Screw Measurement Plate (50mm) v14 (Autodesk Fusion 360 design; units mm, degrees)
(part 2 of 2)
sketch "Labels, Lines (50mm)" plane through (0, 0, 10) normal (0, 0, 1) x axis (1, 0, 0)
  line L1 (-22.7442, -10.4354) -> (-22.7442, -8.6639)
  line L2 (-23.544, -10.4354) -> (-22.7442, -10.4354)
  line L3 (-25.6497, -8.6639) -> (-23.544, -10.4354)
  line L4 (-25.6497, -7.8164) -> (-25.6497, -8.6639)
  line L5 (-23.4986, -7.8164) -> (-25.6497, -7.8164)
  line L6 (-23.4986, -7.3771) -> (-23.4986, -7.8164)
  line L7 (-22.7442, -7.3771) -> (-23.4986, -7.3771)
  line L8 (-22.7442, -7.8164) -> (-22.7442, -7.3771)
  line L9 (-22.09, -7.8164) -> (-22.7442, -7.8164)
  line L10 (-22.09, -8.6639) -> (-22.09, -7.8164)
  line L11 (-22.7442, -8.6639) -> (-22.09, -8.6639)
  line L12 (-24.6001, -8.6639) -> (-23.4986, -8.6639)
  line L13 (-23.4986, -9.6) -> (-24.6001, -8.6639)
  line L14 (-23.4986, -8.6639) -> (-23.4986, -9.6)
  curve K1 (-20.2435, -9.9866) -> (-19.9713, -9.6523)
  curve K2 (-20.7162, -10.1298) -> (-20.2435, -9.9866)
  curve K3 (-21.4348, -9.7168) -> (-20.7162, -10.1298)
  curve K4 (-21.6497, -8.8645) -> (-21.4348, -9.7168)
  curve K5 (-21.3823, -7.8271) -> (-21.6497, -8.8645)
  curve K6 (-20.709, -7.4917) -> (-21.3823, -7.8271)
  curve K7 (-20.2674, -7.6254) -> (-20.709, -7.4917)
  curve K8 (-19.9713, -7.9405) -> (-20.2674, -7.6254)
  curve K9 (-19.6108, -7.5168) -> (-19.9713, -7.9405)
  curve K10 (-19.1142, -7.3771) -> (-19.6108, -7.5168)
  curve K11 (-18.6236, -7.4977) -> (-19.1142, -7.3771)
  curve K12 (-18.2714, -7.7937) -> (-18.6236, -7.4977)
  curve K13 (-18.0888, -8.2306) -> (-18.2714, -7.7937)
  curve K14 (-18.0303, -8.7881) -> (-18.0888, -8.2306)
  curve K15 (-18.1616, -9.638) -> (-18.0303, -8.7881)
  curve K16 (-18.5484, -10.0845) -> (-18.1616, -9.638)
  curve K17 (-19.119, -10.2373) -> (-18.5484, -10.0845)
  curve K18 (-19.6406, -10.094) -> (-19.119, -10.2373)
  curve K19 (-19.9713, -9.6523) -> (-19.6406, -10.094)
  curve K20 (-20.3664, -9.102) -> (-20.6589, -9.2154)
  curve K21 (-20.2554, -8.8) -> (-20.3664, -9.102)
  curve K22 (-20.3652, -8.5255) -> (-20.2554, -8.8)
  curve K23 (-20.6493, -8.418) -> (-20.3652, -8.5255)
  curve K24 (-20.9442, -8.5302) -> (-20.6493, -8.418)
  curve K25 (-21.0576, -8.8167) -> (-20.9442, -8.5302)
  curve K26 (-20.9466, -9.1044) -> (-21.0576, -8.8167)
  curve K27 (-20.6589, -9.2154) -> (-20.9466, -9.1044)
  curve K28 (-18.774, -9.1271) -> (-19.1524, -9.268)
  curve K29 (-18.6272, -8.8048) -> (-18.774, -9.1271)
  curve K30 (-18.7764, -8.492) -> (-18.6272, -8.8048)
  curve K31 (-19.1548, -8.3536) -> (-18.7764, -8.492)
  curve K32 (-19.5344, -8.4932) -> (-19.1548, -8.3536)
  curve K33 (-19.6824, -8.8167) -> (-19.5344, -8.4932)
  curve K34 (-19.5392, -9.1331) -> (-19.6824, -8.8167)
  curve K35 (-19.1524, -9.268) -> (-19.5392, -9.1331)
  line L15 (-14.09, -11.2806) -> (-17.6497, -11.2806)
  line L16 (-14.09, -12.2642) -> (-14.09, -11.2806)
  line L17 (-16.4225, -12.2642) -> (-14.09, -12.2642)
  curve K36 (-16.1289, -12.7262) -> (-16.4225, -12.2642)
  curve K37 (-15.914, -13.286) -> (-16.1289, -12.7262)
  line L18 (-16.7114, -13.286) -> (-15.914, -13.286)
  curve K38 (-17.0958, -12.5149) -> (-16.7114, -13.286)
  curve K39 (-17.6497, -12.0852) -> (-17.0958, -12.5149)
  line L19 (-17.6497, -11.2806) -> (-17.6497, -12.0852)
  line L20 (-14.09, -10.2946) -> (-14.09, -7.3771)
  curve K40 (-14.9029, -9.9902) -> (-14.09, -10.2946)
  curve K41 (-15.8018, -9.0364) -> (-14.9029, -9.9902)
  curve K42 (-16.2841, -8.4897) -> (-15.8018, -9.0364)
  curve K43 (-16.5968, -8.3703) -> (-16.2841, -8.4897)
  curve K44 (-16.8702, -8.4885) -> (-16.5968, -8.3703)
  curve K45 (-16.9836, -8.7857) -> (-16.8702, -8.4885)
  curve K46 (-16.8666, -9.0901) -> (-16.9836, -8.7857)
  curve K47 (-16.4536, -9.2489) -> (-16.8666, -9.0901)
  line L21 (-16.5324, -10.2229) -> (-16.4536, -9.2489)
  curve K48 (-17.1734, -10.0129) -> (-16.5324, -10.2229)
  curve K49 (-17.5267, -9.5819) -> (-17.1734, -10.0129)
  curve K50 (-17.6497, -8.812) -> (-17.5267, -9.5819)
  curve K51 (-17.5327, -8.0134) -> (-17.6497, -8.812)
  curve K52 (-17.1734, -7.5645) -> (-17.5327, -8.0134)
  curve K53 (-16.6302, -7.401) -> (-17.1734, -7.5645)
  curve K54 (-16.0191, -7.5884) -> (-16.6302, -7.401)
  curve K55 (-15.3792, -8.27) -> (-16.0191, -7.5884)
  curve K56 (-15.0951, -8.6627) -> (-15.3792, -8.27)
  curve K57 (-14.8826, -8.8955) -> (-15.0951, -8.6627)
  line L22 (-14.8826, -7.3771) -> (-14.8826, -8.8955)
  line L23 (-14.09, -7.3771) -> (-14.8826, -7.3771)
  line L24 (-10.09, -11.3236) -> (-13.6497, -11.3236)
  line L25 (-10.09, -12.3072) -> (-10.09, -11.3236)
  line L26 (-12.4225, -12.3072) -> (-10.09, -12.3072)
  curve K58 (-12.1289, -12.7692) -> (-12.4225, -12.3072)
  curve K59 (-11.914, -13.329) -> (-12.1289, -12.7692)
  line L27 (-12.7114, -13.329) -> (-11.914, -13.329)
  curve K60 (-13.0958, -12.5579) -> (-12.7114, -13.329)
  curve K61 (-13.6497, -12.1281) -> (-13.0958, -12.5579)
  line L28 (-13.6497, -11.3236) -> (-13.6497, -12.1281)
  line L29 (-12.6828, -8.418) -> (-12.8021, -7.4511)
  curve K62 (-12.9693, -8.5458) -> (-12.6828, -8.418)
  curve K63 (-13.0528, -8.7666) -> (-12.9693, -8.5458)
  curve K64 (-12.8141, -9.1343) -> (-13.0528, -8.7666)
  curve K65 (-12.0787, -9.2751) -> (-12.8141, -9.1343)
  curve K66 (-12.3402, -8.917) -> (-12.0787, -9.2751)
  curve K67 (-12.4249, -8.492) -> (-12.3402, -8.917)
  curve K68 (-12.0907, -7.7006) -> (-12.4249, -8.492)
  curve K69 (-11.2431, -7.3771) -> (-12.0907, -7.7006)
  curve K70 (-10.6105, -7.5406) -> (-11.2431, -7.3771)
  curve K71 (-10.1771, -7.9943) -> (-10.6105, -7.5406)
  curve K72 (-10.0303, -8.7212) -> (-10.1771, -7.9943)
  curve K73 (-10.2094, -9.564) -> (-10.0303, -8.7212)
  curve K74 (-10.7812, -10.0713) -> (-10.2094, -9.564)
  curve K75 (-11.8209, -10.2611) -> (-10.7812, -10.0713)
  curve K76 (-13.2092, -9.8624) -> (-11.8209, -10.2611)
  curve K77 (-13.6497, -8.7571) -> (-13.2092, -9.8624)
  curve K78 (-13.553, -8.0969) -> (-13.6497, -8.7571)
  curve K79 (-13.2701, -7.6946) -> (-13.553, -8.0969)
  curve K80 (-12.8021, -7.4511) -> (-13.2701, -7.6946)
  curve K81 (-10.7979, -9.0985) -> (-11.2431, -9.2417)
  curve K82 (-10.6367, -8.7475) -> (-10.7979, -9.0985)
  curve K83 (-10.7824, -8.4276) -> (-10.6367, -8.7475)
  curve K84 (-11.2169, -8.2987) -> (-10.7824, -8.4276)
  curve K85 (-11.6681, -8.4324) -> (-11.2169, -8.2987)
  curve K86 (-11.8233, -8.7642) -> (-11.6681, -8.4324)
  curve K87 (-11.6729, -9.1044) -> (-11.8233, -8.7642)
  curve K88 (-11.2431, -9.2417) -> (-11.6729, -9.1044)
  line L30 (-6.09, -13.5701) -> (-6.09, -10.6527)
  curve K89 (-6.9029, -13.2657) -> (-6.09, -13.5701)
  curve K90 (-7.8018, -12.312) -> (-6.9029, -13.2657)
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extrude "Extrude6" add sketch "Labels, Lines (50mm)" + "Labels, Pockets (M5, 4mm)" blind 0.4
place_component sketch "Labels, Lines (50mm)" + "Labels, Pockets (M5, 4mm)"
extrude "Extrude1" new body sketch "Labels, Lines (50mm)" + "Labels, Pockets (M5, 4mm)" blind 0.4
position "Position2"
copy_paste_bodies "CopyPasteBodies5"
move "Move3"
sketch "Mount Holes (Hex)" plane through (0, 0, 0) normal (0, 0, 1) x axis (1, 0, 0)
  line L1 (-27, 18) -> (-27, 10)
  line L2 (-27, 0) -> (-27, -8)
  line L3 (27, 26) -> (-31, 26)
  line L4 (-31, 26) -> (-31, 18)
  line L5 (-31, -26) -> (-31, -8)
  line L6 (27, -26) -> (-31, -26)
  line L7 (-27, 25.25) -> (-27, 18.3107)
  line L8 (-27, 25.1578) -> (-24.075, 23.4691)
  line L9 (-29.925, 23.4691) -> (-27, 25.1578)
  line L10 (-29.925, 20.0916) -> (-29.925, 23.4691)
  line L11 (-27, 18.4028) -> (-29.925, 20.0916)
  line L12 (-24.075, 20.0916) -> (-27, 18.4028)
  line L13 (-24.075, 23.4691) -> (-24.075, 20.0916)
  line L14 (-27, -15.9078) -> (-29.925, -14.2191)
  line L15 (-24.075, -14.2191) -> (-27, -15.9078)
  line L16 (-24.075, -10.8416) -> (-24.075, -14.2191)
  line L17 (-27, -9.1528) -> (-24.075, -10.8416)
  line L18 (-29.925, -10.8416) -> (-27, -9.1528)
  line L19 (-29.925, -14.2191) -> (-29.925, -10.8416)
  line L20 (24, 25.25) -> (-28, 25.25)
  line L21 (-30.25, 18.3107) -> (-27, 18.3107)
  line L22 (-27, -8.3107) -> (-30.25, -8.3107)
  line L23 (-25.3, -16.75) -> (-27, -16.75)
  line L24 (-27, -16.75) -> (-27, -8.3107)
  circle C1 centre (-27, 21.7803) radius 1.625
  circle C2 centre (-27, -12.5303) radius 1.625
  circle C3 centre (-27, 21.7803) radius 2.57
  circle C4 centre (-27, -12.5303) radius 2.57
  arc A1 centre (-25.3, -20) radius 3.25 clockwise from (-28.55, -20) to (-22.05, -20)
  point P16 (-27, 21.7803)
  point P24 (-27, 21.7803)
  point P26 (-27, -12.5303)
  point P33 (-27, -12.5303)
  point P15 (-27, 25.25)
  point P14 (-27, 18.3107)
  point P36 (-27, 18.3107)
  point P44 (-25.3, -16.75)
  point P43 (-27, -16.75)
  point P46 (-27, -16.75)
  point P39 (-27, -8.3107)
  point P45 (-27, -8.3107)
  perpendicular L3 L7
  midpoint L7 P16
  coincident P16 P24
  concentric C1 C3
  concentric C2 C4
  coincident P26 P33
  vertical L10
  vertical L19
  coincident P15 L20
  coincident P14 L21
  coincident P14 P36
  horizontal L23
  tangent A1 L23
  coincident A1 P44
  vertical L24
  coincident P43 P46
  coincident P39 P45
  midpoint P26 L24
  dimension "diaMountHole" diameter C2 = 3.25
  dimension "diaMountHole2" diameter C1 = 3.25 (= "diaMountHole")
  dimension "diaMountHex" distance L10 L13 = 5.85
  dimension "diaMagPost" diameter C3 = 5.14
  dimension "diaMagPost2" diameter C4 = 5.14 (= "diaMagPost")
  dimension "diaMountHex2" distance L15 L18 = 5.85 (= "diaMountHex")
extrude "Extrude7" cut sketch "Mount Holes (Hex)" profile of C1 C2 to an object
extrude "Extrude8" sketch "Mount Holes (Hex)" profile of C1 C2 L8 L9 L10 L11 L12 L13 C3 C4 L14 L15 L16 L17 L18 L19 blind -2.65
extrude "Extrude9" cut sketch "Mount Holes (Hex)" profile of C1 C2 C3 C4 along normal blind 5
move "Move4"
copy_paste_bodies "CopyPasteBodies11"
move "Move12"
base_feature "Base Feature1"
base_feature "Base Feature1"
rectangular_pattern "舁}" uSpaceDistance 20 vSpaceDistance 0
joint "Assemble1" alignAngle 0 alignOffsetX 0 alignOffsetY 0 alignOffsetZ 0
joint "Assemble2" alignAngle 0 alignOffsetX 0 alignOffsetY 0 alignOffsetZ 0
joint "Assemble3" alignAngle 0 alignOffsetX 0 alignOffsetY 0 alignOffsetZ 0
joint "Assemble4" alignAngle 0 alignOffsetX 0 alignOffsetY 0 alignOffsetZ 0
copy_paste "CutPaste1"
copy_paste "CutPaste2"
copy_paste "CutPaste3"
copy_paste "CutPaste4"
copy_paste_bodies "CopyPasteBodies6"
move "Move5"
sketch "Hook Hanger" plane through (0, 0, 0) normal (0, 0, 1) x axis (1, 0, 0)
  line L1 (-28, 26) -> (24, 26)
  line L2 (-31, -8.3107) -> (-31, -0.75)
  line L3 (-38, -23) -> (-31, -23)
  line L4 (-38, 23) -> (-38, -23)
  line L5 (-31, 23) -> (-38, 23)
  line L6 (-31, 0) -> (-38, 0)
  line L7 (-31, 0) -> (-31, -0.75)
  line L8 (-36, 15) -> (-30.4, 15)
  line L9 (-36, -15) -> (-30.4, -15)
  line L10 (-38, -17) -> (-30.4, -17)
  line L11 (-30.4, 17) -> (-38, 17)
  line L12 (-36, -17) -> (-36, -15)
  line L13 (-38, -15) -> (-36, -15)
  line L14 (-36, 17) -> (-36, 15)
  line L15 (-37, 17) -> (-37, -15)
  line L16 (-41.5, 0) -> (-39.5, 0)
  line L17 (-38, 17) -> (-38, 5.1235)
  line L18 (-38, 5.1235) -> (-38, 2.8723)
  line L19 (-38, -5.1235) -> (-38, -17)
  line L20 (-38, 2.8723) -> (-38, -2.8723)
  line L21 (-38, -2.8723) -> (-38, -5.1235)
  line L22 (-36, -3.5) -> (-36, -15)
  line L23 (-36, 15) -> (-36, 3.5)
  line L24 (-36, 0) -> (-36, -3.5)
  line L25 (-36, 3.5) -> (-36, 0)
  line L26 (-30.4, -23) -> (-30.4, -0.75)
  line L27 (-30.4, 10.75) -> (-30.4, 23)
  line L28 (-31, 23) -> (-31, 10.75)
  line L29 (-31, -0.75) -> (-31, -23)
  line L30 (-27, -8.3107) -> (-27, 0)
  line L31 (-27, 10) -> (-27, 18.3107)
  line L32 (-27, -25.909) -> (-27, -8.3107)
  line L33 (-27, -25.909) -> (-28.7333, -25.909)
  line L34 (-27, -23) -> (-30.4, -23)
  line L35 (-28.7, 23) -> (-28.7, -23)
  line L36 (-28.7, 23) -> (-30.4, 23)
  line L37 (-28.7, -16) -> (-36, -16)
  line L38 (-28.7, 16) -> (-36, 16)
  line L39 (-34.2, -15) -> (-34.2, -17)
  line L40 (-28.7, -16.575) -> (-34.2, -16.575)
  line L41 (-28.7, -16.475) -> (-34.2, -16.475)
  line L42 (-28.7, -16.225) -> (-34.2, -16.225)
  line L43 (-28.7, -16.125) -> (-34.2, -16.125)
  line L44 (-28.7, -15.875) -> (-34.2, -15.875)
  line L45 (-34.2, -15.775) -> (-28.7, -15.775)
  line L46 (-28.7, -15.525) -> (-34.2, -15.525)
  line L47 (-28.7, -15.425) -> (-34.2, -15.425)
  line L48 (-31.45, -15.525) -> (-31.45, -15.425)
  line L49 (-31.45, -15.775) -> (-31.45, -15.525)
  line L50 (-31.45, -15.875) -> (-31.45, -15.775)
  line L51 (-31.45, -16.125) -> (-31.45, -15.875)
  line L52 (-31.45, -16.225) -> (-31.45, -16.125)
  line L53 (-31.45, -16.475) -> (-31.45, -16.225)
  line L54 (-31.45, -16.575) -> (-31.45, -16.475)
  line L55 (-28.7, 15.425) -> (-34.2, 15.425)
  line L56 (-28.7, 15.525) -> (-34.2, 15.525)
  line L57 (-34.2, 15.775) -> (-28.7, 15.775)
  line L58 (-28.7, 15.875) -> (-34.2, 15.875)
  line L59 (-28.7, 16.125) -> (-34.2, 16.125)
  line L60 (-28.7, 16.225) -> (-34.2, 16.225)
  line L61 (-28.7, 16.575) -> (-34.2, 16.575)
  line L62 (-28.7, 16.475) -> (-34.2, 16.475)
  line L63 (-34.2, 15.525) -> (-34.2, 15.425)
  line L64 (-34.2, 15.875) -> (-34.2, 15.775)
  line L65 (-34.2, 16.225) -> (-34.2, 16.125)
  line L66 (-34.2, 16.575) -> (-34.2, 16.475)
  arc A1 centre (-28, 23) radius 3 clockwise from (-31, 23) to (-28, 26)
  arc A2 centre (-28, -23) radius 3 clockwise from (-28.7333, -25.909) to (-31, -23)
  arc A3 centre (-36, 0) radius 3.5 clockwise from (-36, -3.5) to (-36, 3.5)
  arc A4 centre (-36, 0) radius 5.5 clockwise from (-38, 5.1235) to (-36, 5.5)
  arc A5 centre (-36, 0) radius 5.5 clockwise from (-36, -5.5) to (-38, -5.1235)
  arc A6 centre (-36, 0) radius 5.5 clockwise from (-38, -5.1235) to (-41.5, 0)
  arc A7 centre (-36, 0) radius 5.5 clockwise from (-41.5, 0) to (-38, 5.1235)
  arc A8 centre (-30.25, 10.75) radius 0.75 clockwise from (-30.537, 10.0571) to (-31, 10.75)
  point P6 (-31, -23)
  point P11 (-31, -23)
  point P7 (-31, 23)
  point P14 (-31, 23)
  point P15 (-38, 0)
  point P4 (-31, -0.75)
  point P17 (-31, -0.75)
  point P23 (-38, -17)
  point P24 (-38, 17)
  point P26 (-36, -17)
  point P27 (-38, -15)
  point P28 (-36, 17)
  point P29 (-37, -15)
  point P30 (-37, 17)
  point P32 (-36, 3.5)
  point P37 (-39.5, 0)
  point P34 (-36, 0)
  point P39 (-38, -5.1235)
  point P42 (-38, 5.1235)
  point P44 (-38, 2.8723)
  point P45 (-38, -2.8723)
  point P18 (-30.4, 15)
  point P25 (-30.4, 17)
  point P20 (-30.4, -15)
  point P22 (-30.4, -17)
  point P35 (-36, -5.5)
  point P36 (-36, 5.5)
  point P58 (-27, -8.3107)
  point P61 (-27, -8.3107)
  point P9 (-28.7333, -25.909)
  point P63 (-28.7333, -25.909)
  point P64 (-27, -25.909)
  point P62 (-27, -25.909)
  point P50 (-30.4, -23)
  point P65 (-30.4, -23)
  point P66 (-27, -23)
  point P67 (-28.7, -23)
  point P51 (-30.4, 23)
  point P69 (-30.4, 23)
  point P70 (-28.7, 23)
  point P68 (-28.7, 23)
  point P71 (-36, -16)
  point P72 (-28.7, -16)
  point P73 (-36, 16)
  point P74 (-28.7, 16)
  point P75 (-34.2, -17)
  point P76 (-34.2, -15)
  point P77 (-34.2, -16.575)
  point P78 (-28.7, -16.575)
  point P79 (-34.2, -16.475)
  point P80 (-28.7, -16.475)
  point P81 (-34.2, -16.225)
  point P82 (-28.7, -16.225)
  point P83 (-34.2, -16.125)
  point P84 (-28.7, -16.125)
  point P85 (-34.2, -15.875)
  point P86 (-28.7, -15.875)
  point P87 (-28.7, -15.775)
  point P88 (-34.2, -15.775)
  point P89 (-34.2, -15.525)
  point P90 (-28.7, -15.525)
  point P91 (-34.2, -15.425)
  point P92 (-28.7, -15.425)
  point P93 (-31.45, -15.425)
  point P94 (-31.45, -15.525)
  point P95 (-31.45, -15.775)
  point P96 (-31.45, -15.875)
  point P97 (-31.45, -16.125)
  point P98 (-31.45, -16.225)
  point P99 (-31.45, -16.475)
  point P100 (-31.45, -16.575)
  point P113 (-34.2, 16.575)
  point P114 (-28.7, 16.575)
  point P115 (-34.2, 16.475)
  point P116 (-28.7, 16.475)
  point P111 (-34.2, 16.225)
  point P112 (-28.7, 16.225)
  point P109 (-34.2, 16.125)
  point P110 (-28.7, 16.125)
  point P107 (-34.2, 15.875)
  point P108 (-28.7, 15.875)
  point P105 (-28.7, 15.775)
  point P106 (-34.2, 15.775)
  point P103 (-34.2, 15.525)
  point P104 (-28.7, 15.525)
  point P101 (-34.2, 15.425)
  point P102 (-28.7, 15.425)
  point P21 (-36, -15)
  coincident P6 P11
  coincident P7 P14
  horizontal L5
  horizontal L3
  vertical L4
  midpoint L4 P15
  coincident P4 P17
  symmetric L6 L8 L9
  vertical L22
  coincident L4 P23
  coincident L4 P24
  horizontal L11
  horizontal L10
  coincident L10 P26
  coincident P27 L19
  horizontal L13
  vertical L12
  equal L12 L13
  coincident L11 P28
  perpendicular L11 L14
  equal L12 L14
  horizontal L9
  horizontal L8
  midpoint L13 P29
  coincident L11 P30
  perpendicular L11 L15
  horizontal L16
  concentric A3 A4
  equal L12 L16
  coincident P32 L22
  coincident A3 P37
  coincident P34 L22
  coincident L6 P34
  vertical L7
  coincident L4 P39
  concentric A4 A5
  concentric A4 A6
  coincident L4 P42
  concentric A4 A7
  coincident A3 P44
  coincident A3 P45
  vertical L21
  vertical L20
  vertical L23
  coincident P18 L27
  coincident P25 L27
  coincident P20 L26
  coincident P22 L26
  coincident P35 L22
  coincident P36 L23
  coincident P58 P61
  coincident P9 P63
  horizontal L33
  coincident L32 P64
  coincident P62 P64
  vertical L32
  coincident P50 P65
  coincident L32 P66
  midpoint L34 P67
  coincident P51 P69
  coincident L35 P70
  horizontal L36
  vertical L35
  horizontal L34
  coincident P68 P70
  midpoint L12 P71
  coincident L35 P72
  midpoint L14 P73
  coincident L35 P74
  perpendicular L35 L38
  midpoint L10 P75
  coincident L9 P76
  perpendicular L9 L39
  coincident L39 P77
  coincident L35 P78
  coincident L39 P79
  coincident L35 P80
  coincident L39 P81
  coincident L35 P82
  coincident L39 P83
  coincident L35 P84
  horizontal L40
  horizontal L41
  horizontal L42
  horizontal L43
  coincident L39 P85
  coincident L35 P86
  coincident L35 P87
  coincident L39 P88
  coincident L39 P89
  coincident L35 P90
  coincident L39 P91
  coincident L35 P92
  horizontal L47
  horizontal L44
  horizontal L45
  horizontal L46
  midpoint L47 P93
  midpoint L46 P94
  perpendicular L46 L48
  midpoint L45 P95
  perpendicular L45 L49
  midpoint L44 P96
  perpendicular L44 L50
  midpoint L43 P97
  perpendicular L43 L51
  midpoint L42 P98
  perpendicular L42 L52
  midpoint L41 P99
  perpendicular L41 L53
  midpoint L40 P100
  perpendicular L40 L54
  equal L52 L54
  equal L50 L52
  equal L48 L50
  equal L51 L53
  equal L49 L51
  symmetric L37 L43 L44
  symmetric L6 P77 P113
  symmetric L6 P78 P114
  symmetric L6 P79 P115
  symmetric L6 P80 P116
  symmetric L6 P81 P111
  symmetric L6 P82 P112
  symmetric L6 P83 P109
  symmetric L6 P84 P110
  symmetric L6 P85 P107
  symmetric L6 P86 P108
  symmetric L6 P87 P105
  symmetric L6 P88 P106
  symmetric L6 P89 P103
  symmetric L6 P90 P104
  symmetric L6 P91 P101
  symmetric L6 P92 P102
  dimension "radiusHangerCenter" radius A3 = 3.5
  dimension "thicknessHanger" distance P21 P26 = 2
  dimension "widthHanger" distance L8 L9 = 30
  dimension "heightHanger" distance P11 P21 = 5
  dimension "widthHangerRigidity" distance P99 P100 = 0.1
  dimension "spacingHangerRigidity" distance P98 P99 = 0.25
extrude "Extrude10" add sketch "Hook Hanger" profile of L8 L9 L10 L11 A3 A6 A7 L17 L19 L22 L23 L26 L27 L39 L40 L41 L42 L43 L44 L45 L46 L47 L55 L56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 along normal blind 2 (= "thicknessHanger") named "depthHanger"
fillet "Fillet5" radius 2 (= "thicknessHanger") named "radHangOutlineInner"
fillet "Fillet6" radius 4 (= "radHangOutlineInner * 2") named "radHangOutlineOuter"
chamfer "Chamfer4" distance 0.6 (= "thicknessHanger * 0.3") named "depthHangBottomChamfer"
fillet "Fillet4" radius 1.5 (= "thicknessHanger * 0.75") named "radHangMount"
fillet "Fillet3" radius 0.6 (= "thicknessHanger * 0.3") named "radHangTop"
move "Move6"
copy_paste_bodies "CopyPasteBodies12"
move "Move13"
extrude "Extrude24" sketch "Big Plane (Horizontal)" profile of L1 L2 L3 L4 to an object
copy_paste_bodies "CopyPasteBodies13"
move "Move14"
base_feature "Base Feature1"
base_feature "Base Feature1"
base_feature "Base Feature1"
base_feature "Base Feature1"
base_feature "Base Feature1"
base_feature "Base Feature1"
base_feature "Base Feature1"
base_feature "Base Feature1"
base_feature "Base Feature1"
base_feature "Base Feature1"
joint "Assemble5" alignAngle 0 alignOffsetX 0 alignOffsetY 0 alignOffsetZ 0
joint "Assemble6" alignAngle 0 alignOffsetX 0 alignOffsetY 0 alignOffsetZ 0
joint "Assemble7" alignAngle 0 alignOffsetX 0 alignOffsetY 0 alignOffsetZ 0
joint "Assemble8" alignAngle 0 alignOffsetX 0 alignOffsetY 0 alignOffsetZ 0
joint "Assemble9" alignAngle 0 alignOffsetX 0 alignOffsetY 0 alignOffsetZ 0
joint "Assemble10" alignAngle 0 alignOffsetX 0 alignOffsetY 0 alignOffsetZ 0
joint "Assemble11" alignAngle 0 alignOffsetX 0 alignOffsetY 0 alignOffsetZ 0
joint "Assemble12" alignAngle 0 alignOffsetX 0 alignOffsetY 0 alignOffsetZ 0
joint "Assemble13" alignAngle 0 alignOffsetX 0 alignOffsetY 0 alignOffsetZ 0
joint "Assemble14" alignAngle 0 alignOffsetX 0 alignOffsetY 0 alignOffsetZ 0
copy_paste_bodies "CopyPasteBodies1"
move "Move1"
base_feature "Base Feature1"
base_feature "Base Feature1"
sketch "Base Outline" plane through (0, 0, 0) normal (0, 0, 1) x axis (1, 0, 0)
  circle C1 centre (0, 0) radius 6.05
  circle C2 centre (0, 0) radius 2.5
  circle C3 centre (0, 0) radius 4.75
  point P1 (0, 0)
  point P2 (0, 0)
  point P3 (0, 0)
  point P4 (0, 0)
  coincident P1 P2
  coincident P1 P3
  coincident P1 P4
  dimension "diameterFoot" diameter C1 = 12.1
  dimension "diameterRiser" diameter C2 = 5
  dimension "diameterMagnet" diameter C3 = 9.5
extrude "Extrude1" new body sketch "Base Outline" along normal blind 2.8 named "heightFoot"
extrude "Extrude2" add sketch "Base Outline" profile of C2 along normal blind 11.92 named "heightRiser"
base_feature "Base Feature1"
split "Split1"
remove_body "RemoveBody1"
move "Move1"
joint "Assemble1" alignAngle 0 named "angleJointThreads" alignOffsetX 0 named "offXjointThreads" alignOffsetY 0 named "offYjointThreads" alignOffsetZ -0.1 named "offZjointThreads"
copy_paste_bodies "CutPasteBodies1"
remove_instance "RemoveInstance1"
combine "Combine1"
fillet "Fillet1" radius 1 named "radiusBaseFace"
fillet "Fillet2" radius 0.5 named "radiusRiserBase"
extrude "Extrude3" cut blind 1 named "depthMagClearance" Side1WallThickness 0.25 named "thicknessMagClearance"
fillet "Fillet3" radius 0.2 named "radiusMagFace"
sketch "Vertical Measurements" plane through (0, 0, 0) normal (0, 1, 0) x axis (1, 0, 0)
  line L1 (6.05, 0) -> (-6.05, 0)
  line L2 (6.05, -2.8) -> (-6.05, -2.8)
  point P2 (0, -16.82)
  point P3 (0, 0)
  point P4 (-2.5, -11.92)
  point P5 (-6.05, 0)
  point P9 (-6.05, -2.8)
  dimension "heightTotal" distance P2 P3 = 16.82
  dimension "heightBaseRiser" distance P4 L1 = 11.92
  dimension "heightRiserOnly" distance P4 L2 = 9.12
  dimension "heightBaseOnly" distance P5 P9 = 2.8
  dimension "heightThreadsOnly" distance P2 P4 = 4.9
sketch "Base Outline" plane through (0, 0, 0) normal (0, 0, 1) x axis (1, 0, 0)
  circle C1 centre (0, 0) radius 6.05
  circle C2 centre (0, 0) radius 2.5
  circle C3 centre (0, 0) radius 4.75
  point P1 (0, 0)
  point P2 (0, 0)
  point P3 (0, 0)
  point P4 (0, 0)
  coincident P1 P2
  coincident P1 P3
  coincident P1 P4
  dimension "diameterFoot_1" diameter C1 = 12.1
  dimension "diameterRiser_1" diameter C2 = 5
  dimension "diameterMagnet_1" diameter C3 = 9.5
extrude "Extrude1" new body sketch "Base Outline" along normal blind 2.8 named "heightFoot_1"
extrude "Extrude2" add sketch "Base Outline" profile of C2 along normal blind 11.92 named "heightRiser_1"
base_feature "Base Feature1"
split "Split1"
remove_body "RemoveBody1"
move "Move1"
joint "Assemble1" alignAngle 0 named "angleJointThreads_1" alignOffsetX 0 named "offXjointThreads_1" alignOffsetY 0 named "offYjointThreads_1" alignOffsetZ -0.1 named "offZjointThreads_1"
copy_paste_bodies "CutPasteBodies1"
remove_instance "RemoveInstance1"
combine "Combine1"
fillet "Fillet1" radius 1 named "radiusBaseFace_1"
fillet "Fillet2" radius 0.5 named "radiusRiserBase_1"
extrude "Extrude3" cut blind 1 named "depthMagClearance_1" Side1WallThickness 0.25 named "thicknessMagClearance_1"
fillet "Fillet3" radius 0.2 named "radiusMagFace_1"
sketch "Vertical Measurements" plane through (0, 0, 0) normal (0, 1, 0) x axis (1, 0, 0)
  line L1 (6.05, 0) -> (-6.05, 0)
  line L2 (6.05, -2.8) -> (-6.05, -2.8)
  point P2 (0, -16.82)
  point P3 (0, 0)
  point P4 (-2.5, -11.92)
  point P5 (-6.05, 0)
  point P9 (-6.05, -2.8)
  dimension "heightTotal_1" distance P2 P3 = 16.82
  dimension "heightBaseRiser_1" distance P4 L1 = 11.92
  dimension "heightRiserOnly_1" distance P4 L2 = 9.12
  dimension "heightBaseOnly_1" distance P5 P9 = 2.8
  dimension "heightThreadsOnly_1" distance P2 P4 = 4.9
copy_paste_bodies "CutPasteBodies1"
copy_paste_bodies "CopyPasteBodies2"
move "Move1"
position "Position4"
copy_paste_bodies "CutPasteBodies3"
move "Move2"
joint "Assemble3" alignAngle 180 alignOffsetX 0 alignOffsetY 0 alignOffsetZ 0
joint "Assemble4" alignAngle 180 alignOffsetX 0 alignOffsetY 0 alignOffsetZ 0
rectangular_pattern "R-Pattern1" uSpaceDistance 60 vSpaceDistance 0
rectangular_pattern "R-Pattern2" uSpaceDistance -58.455 vSpaceDistance 0
base_feature "Base Feature1"
joint "Assemble15" alignAngle 180 alignOffsetX 0 alignOffsetY -4 alignOffsetZ 0
base_feature "Base Feature1"
joint "Assemble16" alignAngle 0 alignOffsetX 0 alignOffsetY -0.75 alignOffsetZ 0
base_feature "Base Feature1"
joint "Assemble17" alignAngle 0 alignOffsetX 0 alignOffsetY -4.82 alignOffsetZ 0
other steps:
base_feature "Base Feature1" bodies "Gauge, 50mm, M5 (Mag Feet, Nuts)"
base_feature "Base Feature1" bodies "Gauge, 50mm, M5 (Flipped Demo)"
base_feature "Base Feature2" bodies "Gauge, 50mm, M5 (Hook Hanger)"
base_feature "Base Feature3" bodies "Gauge, 50mm, M5 (Mag Feet, Nuts)"
base_feature "Base Feature1" bodies "Mag Foot"
base_feature "Base Feature1" bodies "Mag Foot"
base_feature "Base Feature9" bodies "Gauge, 50mm, M5 (3)", "Gauge, 50mm, M5 (No Labels)"
base_feature "Base Feature5" bodies "Gauge, 50mm, M5 (1)", "Gauge, 50mm, M5 (Mag Feet, Nuts)"
base_feature "Base Feature11" bodies "Gauge, 50mm, M5 (Mag Feet, Nuts)", "Gauge, 50mm, M5 (Mag Feet, Nuts, Blank)"
base_feature "Base Feature6" bodies "Gauge, 50mm, M5 (2)", "Gauge, 50mm, M5 (Hook Hanger)"
base_feature "Base Feature12" bodies "Gauge, 50mm, M5 (Hook Hanger)", "Gauge, 50mm, M5 (Hook Hanger) (1)"
base_feature "Base Feature13" bodies "Gauge, 50mm, M5", "Gauge, 50mm, M5 (Flipped Demo)"
create_component "CreateComponent3"
create_component "CreateComponent1"
create_component "CreateComponent2"
joint_origin "JointOrigin1"
joint_origin "JointOrigin3"
joint_origin "JointOrigin2"
joint_origin "JointOrigin5"
joint_origin "JointOrigin4"
joint_origin "JointOrigin6"
joint_origin "JointOrigin5"
joint_origin "JointOrigin7"
create_component "CreateComponent3"
remove_instance "RemoveInstance1"
remove_instance "RemoveInstance2"
remove_instance "RemoveInstance3"
remove_instance "RemoveInstance4"
create_component "CreateComponent4" sketch "Labels, Lines (50mm)" + "Labels, Pockets (M5, 4mm)"
create_component "CreateComponent5"
create_component "CreateComponent7"
create_component "CreateComponent8"
create_component "CreateComponent9"
create_component "CreateComponent10"
create_component "CreateComponent11"
create_component "CreateComponent12"
create_component "CreateComponent13"
create_component "CreateComponent14"
create_component "CreateComponent15"
extrude "Extrude1" cut sketch "Outline, Nuts & Inserts" profile of C1 along normal blind 6.8
joint_origin "JointOrigin1"
joint_origin "JointOrigin8"
joint_origin "JointOrigin1"
joint_origin "JointOrigin9"
joint_origin "JointOrigin1"
joint_origin "JointOrigin10"
joint_origin "JointOrigin1"
joint_origin "JointOrigin11"
joint_origin "JointOrigin1"
joint_origin "JointOrigin12"
create_component "CreateComponent5"
create_component "CreateComponent1"
create_component "CreateComponent2"
create_component "CreateComponent3"
create_component "CreateComponent4"
create_component "CreateComponent5"
create_component "CreateComponent6"
create_component "CreateComponent7"
create_component "CreateComponent8"
create_component "CreateComponent9"
create_component "CreateComponent10"
joint_origin "JointOrigin1"
joint_origin "JointOrigin13"
joint_origin "JointOrigin1"
joint_origin "JointOrigin14"
create_component "CreateComponent11"
joint_origin "JointOrigin1"
joint_origin "JointOrigin15"
joint_origin "JointOrigin1"
joint_origin "JointOrigin16"
joint_origin "JointOrigin1"
joint_origin "JointOrigin17"
joint_origin "JointOrigin1"
joint_origin "JointOrigin18"
joint_origin "JointOrigin1"
joint_origin "JointOrigin19"
joint_origin "JointOrigin1"
joint_origin "JointOrigin20"
joint_origin "JointOrigin1"
joint_origin "JointOrigin21"
joint_origin "JointOrigin1"
joint_origin "JointOrigin22"
create_component "CreateComponent12"
create_component "CreateComponent13"
create_component "CreateComponent1"
joint_origin "JointOrigin2"
joint_origin "JointOrigin2"
remove_body "RemoveBody2"
create_component "CreateComponent14"
create_component "CreateComponent1"
joint_origin "JointOrigin2"
joint_origin "JointOrigin2"
remove_body "RemoveBody2"
create_component "CreateComponent15"
remove_body "RemoveBody1"
remove_body "RemoveBody1"
joint_origin "JointOrigin4"
joint_origin "JointOrigin1"
joint_origin "JointOrigin4"
joint_origin "JointOrigin2"
create_component "CreateComponent16"
joint_origin "JointOrigin1"
joint_origin "JointOrigin23"
create_component "CreateComponent17"
joint_origin "JointOrigin1"
joint_origin "JointOrigin24"
create_component "CreateComponent18"
joint_origin "JointOrigin1"
joint_origin "JointOrigin25"
named bodies: "Gauge, 50mm, M5", "Gauge, 50mm, M5 (1)", "Gauge, 50mm, M5 (Mag Feet, Nuts)", "Gauge, 50mm, M5 (2)", "Gauge, 50mm, M5 (Hook Hanger)", "Gauge, 50mm, M5 (3)", "Gauge, 50mm, M5 (No Labels)", "Gauge, 50mm, M5 (Mag Feet, Nuts, Blank)", "Gauge, 50mm, M5 (Hook Hanger) (1)", "Nut, M2 (91828A111) v1", "Nut, M3 (91828A211) v1 (1)", "Nut, M4 (91828A231) v1", "Nut, M5 (91828A241) v1", "Nut, M2.5 (91828A113) v1", "Insert, M3, Short (CNC Kitchen) v2", "Insert, M4, Short (CNC Kitchen) v2", "Insert, M5, Short (CNC Kitchen) v2", "Insert, M2 [3.3x2.5] (McMaster 94459A110) v2", "Insert, M2.5 [4.1x5.9] (McMaster 94459A439) v3", "Gauge, 50mm, M5 (Flipped Demo)", "Mag Foot"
